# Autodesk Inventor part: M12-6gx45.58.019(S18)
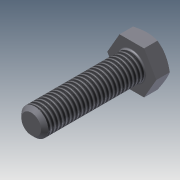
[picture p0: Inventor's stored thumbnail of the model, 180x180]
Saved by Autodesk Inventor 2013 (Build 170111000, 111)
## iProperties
Shininess: 25.0
Length Units: 11269
Angle Units: 11279
Time Units: 11290
Mass Units: 11283
Length Display Precision: 3
Angle Display Precision: 2
Created: 2001-10
Material: Steel, Mild
Document SubType Name: Modeling
Designer: TEvgeniy
Mass: 57.7422 g
Surface Area: 27.2183 cm^2
Volume: 7.34634 cm^3
Density: 7.86 g/cm^3
Density: 0.0
Volumn: 0.0
Area: 0.0
PropertySet Name: Model Information
Control State: 0
Master: False
Checked Out: True
Checked Out Date: 2008-10-15
Last Check In Date: 2008-10-15
Author: TEvgeniy
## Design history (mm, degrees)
sketch "Sketch1"
  geometry: L1 (485.544, 469.325)-(474.575, 469.325); L2 (491.029, 459.825)-(485.544, 469.325); L3 (485.544, 450.325)-(491.029, 459.825); L4 (474.575, 450.325)-(485.544, 450.325); L5 (469.09, 459.825)-(474.575, 450.325); L6 (474.575, 469.325)-(469.09, 459.825); C1 r 9.5 at (480.059, 459.825)
  constraints: 12 end point, 6 tangent, 3 parallel, 1 centre point, 1 horizontal, 1 other
  dimensions: "d1" = 120 deg angle of L1 L2; "d3" = 120 deg angle of L5 L6; "d5" = 19 diameter of C1
extrude "ExtrusionBlind1" new body sketch "Sketch1" distance "d6" = 7.5; taper "d7" = 0 deg
sketch "Sketch2"
  geometry: C1 r 8.4 at (480.059, -459.825)
  constraints: 1 centre point
  dimensions: "d12" = 16.8 diameter of C1
extrude "ExtrusionThru1" sketch "Sketch2" stored distance "d13" = 0.13; taper "d14" = 60 deg
sketch "Sketch3"
  geometry: L1 (469.09, 459.825)-(469.59, 460.691); L2 (474.575, 469.325)-(475.575, 469.325); L3 (485.544, 469.325)-(486.044, 468.459); C1 r 6 at (480.059, 459.825); C2 r 9.5 at (480.059, 459.825)
  constraints: 6 end point, 3 tangent, 2 centre point, 1 coincident
  dimensions: "d16" = 12 diameter of C1
extrude "ExtrusionBlind2" join sketch "Sketch3" distance "d17" = 45; taper "d18" = 0 deg
fillet "Fillet1" dims "d19" = 0.5
chamfer "Chamfer1" distance "d20" = 1.6; stored, may be unused: second distance "d21" = 1.6, angle "d26" = 45 deg
thread "Thread1" dims "d22" = 10, "d23" = 0
body "Solid1"
other parameters: "d0" = 120 deg (derived), "d2" = 120 deg (derived), "d4" = 19 (derived), "d8" = 0, "d9" = 0, "d10" = 0, "d11" = 16.8 (derived), "d15" = 12 (derived)
